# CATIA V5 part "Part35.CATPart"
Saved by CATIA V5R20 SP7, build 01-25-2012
Part number: tige vérin gauche
Bounding box of the stored display mesh (mm): x -12.584 to 14.61, y -32.162 to 26.15, z 42.571 to 50.979
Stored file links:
  F:\Travaux\Modélisations\CFAO_2011\CFAO_2011_MMS\CFAO_2011_MMS_DONE\CFAO_2011_MMS_jboiteux\Catia\Part35.CATPart
  U:\finthinkmotion\stepper.CATProduct
  F:\Travaux\Modélisations\CFAO_2011\CFAO_2011_MMS\CFAO_2011_MMS_DONE\CFAO_2011_MMS_jboiteux\Catia\bati.CATPart
  F:\Travaux\Modélisations\CFAO_2011\CFAO_2011_MMS\CFAO_2011_MMS_DONE\CFAO_2011_MMS_jboiteux\Catia\part4.CATPart
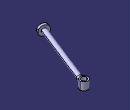
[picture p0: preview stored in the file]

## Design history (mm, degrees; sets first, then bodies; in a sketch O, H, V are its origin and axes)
Parameters
  rayontube = 9 mm {= External.royontubebati}
  longueurpied = 108 mm {= External.longueurpied}
External parameters (linked from other documents)
  External.royontubebati = 9 mm
  External.longueurpied = 108 mm
Sketch1 on Plane2, origin (0, 0, 45.721), H (1, 0, 0), V (0, -1, 0)
  circle A1 centre (11.46, -23) radius 3.15
  point P1 (11.46, -23)
  circle A2 centre (11.46, -23) radius 2.15
  reference projected point E1 (11.46, -23) from Point1
  radius A2 = 2.15 {= rayontube *.7/2-1mm}
  radius A1 = 3.15 {= rayontube *0.7/2}
  coincidence: E1 P1
Set1
  Plane1: linked copy from another document
  Point1: linked copy from another document
  Line1: linked copy from another document
  DatumCurve1: linked copy from another document
  Line2: linked copy from another document
Body1 (main body)
  Plane2: type OffsetPt, RefPlane Plane1, RefPoint Point1
  Pad1: profile Sketch1, direction (0, 0, -1), length 3.15 {= rayontube *0.7/2}, mirrored extent
  Plane3: type Normal, Curve Line1
  Plane4: type OffsetPt, RefPlane Plane3, RefPoint Point1
  Sketch2 on Plane3, origin (41.7191, -5.1088, 20.7052), H (0.9095, -0.3384, 0.2416), V (-0.2182, 0.1063, 0.9701)
    projected circle E1 centre (-30.9862, 33.8578) radius 1.8 from edge of DatumCurve1
  Pad2: profile Sketch2, direction (-0.354, -0.935, 0.0228), length 40.5 {= longueurpied *3/8}, opposite side up to Plane4, offset -6 {= -rayontube /1.5}
  Sketch3 on start face of Pad2, origin (45.4126, 3.1073, 20.2318), H (-0.9095, 0.3384, -0.2416), V (-0.2182, 0.1063, 0.9701)
    circle A1 centre (31.4506, 34.2498) radius 2
    point P1 (31.4506, 34.2498)
    reference projected point E1 (31.4506, 34.2498) from Line1
    radius A1 = 2 {= rayontube *20/90}
    coincidence: E1 P1
  Pad3: profile Sketch3, direction (0.354, 0.935, -0.0228), up to face of Pad1 from Sketch1.A1
  Sketch4 on end face of Pad2, origin (23.2155, -41.3773, 22.4621), H (0.9095, -0.3384, 0.2416), V (-0.2182, 0.1063, 0.9701)
    circle A1 centre (-26.8558, 31.9706) radius 3.95
    point P1 (-26.8558, 31.9706)
    reference projected point E1 (-26.8558, 31.9706) from Line2
    radius A1 = 3.95 {= rayontube *1.1/2-1mm}
    coincidence: E1 P1
  Pad4: profile Sketch4, direction (-0.354, -0.935, 0.0228), length 2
